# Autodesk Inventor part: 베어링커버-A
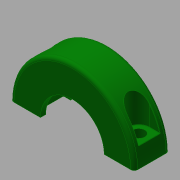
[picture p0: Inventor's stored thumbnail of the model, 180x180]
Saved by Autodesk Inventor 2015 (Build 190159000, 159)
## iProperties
Created: 2018-01
Part Number: 베어링커버-A
Material: 알루미늄 6061
Document SubType Name: Modeling
Designer: mduedu
Density: 2.71 g/cm^3
Appearance: 진녹색
Author: mduedu
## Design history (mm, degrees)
sketch "스케치1"
  geometry: L1 (-17.5, 0)-(17.5, 0); A1 r 17.5 centre (0, 0) between (-17.5, 0) and (17.5, 0); 2 further points
  constraints: 2 coincident, 2 end point, 2 point on circle, 1 centre point, 1 horizontal, 1 midpoint
  dimensions: "d0" = 35 diameter of A1
extrude "돌출1" new body sketch "스케치1" stored distance "d1" = 10; taper "d2" = 0 deg
sketch "스케치2"
  geometry: C1 r 11 at (0, 0); C2 r 9 at (0, 0); 1 further point
  constraints: 2 centre point, 2 coincident
  dimensions: "d3" = 22 diameter of C1; "d4" = 18 diameter of C2
extrude "돌출2" cut sketch "스케치2" stored distance "d5" = 7; taper "d6" = 0 deg
extrude "돌출3" cut sketch "스케치2" stored distance "d7" = 7; taper "d8" = 0 deg
fillet "모깎기1" dims "d9" = 0.3
fillet "모깎기2" dims "d10" = 1
node "작업 평면1"
sketch "스케치3"
  geometry: L1 (-15.5, -3.5)-(33.5, -3.5) reference; L2 (-4.771, -6.5)-(-7.771, -6.5); L3 (-7.771, -6.5)-(-7.771, -0.5); L4 (-7.771, -0.5)-(-4.771, -0.5); L5 (-0.46, -7)-(1.517, -7) reference; L6 (1.517, -7)-(1.517, -8.5) reference; L7 (1.517, -8.5)-(-6.724, -8.5) reference; L8 (-7.771, -7.5)-(-7.771, 0.5) reference; L9 (-6.724, 1.5)-(1.517, 1.5) reference; L10 (1.517, 1.5)-(1.517, 0) reference; L11 (1.517, 0)-(-0.46, 0) reference; L12 (-0.798, -0.3)-(-0.798, -6.7) reference; L13 (18.798, -6.7)-(18.798, -0.3) reference; L14 (18.46, 0)-(16.483, 0) reference; L15 (16.483, 0)-(16.483, 1.5) reference; L16 (16.483, 1.5)-(24.724, 1.5) reference; L17 (25.771, 0.5)-(25.771, -7.5) reference; L18 (24.724, -8.5)-(16.483, -8.5) reference; L19 (16.483, -8.5)-(16.483, -7) reference; L20 (16.483, -7)-(18.46, -7) reference; A1 r 3 centre (-4.771, -3.5) between (-4.771, -6.5) and (-4.771, -0.5); 1 further point
  constraints: 6 end point, 2 point on circle, 2 tangent, 1 centre point, 1 collinear, 1 horizontal, 1 parallel, 1 perpendicular, 1 point on line, 8 other
  dimensions: "d12" = 6 distance between parallel lines of L4 L2; "d14" = 6 dimension on A1 L3
extrude "돌출4" cut sketch "스케치3" stored distance "d15" = 0; taper "d16" = 0 deg
sketch "스케치4"
  geometry: 7 further points
  constraints: 4 vertical alignment, 2 horizontal alignment
sketch "스케치5"
  geometry: 2 further points
  constraints: 2 other
hole "구멍1" sketch "스케치5" at (-22.771, 3.5), (4.771, 3.5) diameter "d17" = 3.4; stored, may be unused: countersink angle "d21" = 90 deg, drill point angle "d23" = 0 deg; dims "d18" = 6, "d19" = 4, "d20" = 2, "d22" = 8
fillet "모깎기3" dims "d24" = 0.1
node "솔리드1"
mirror "대칭1"
node "절단 모서리 투영1"
other parameters: "d11" = -5
